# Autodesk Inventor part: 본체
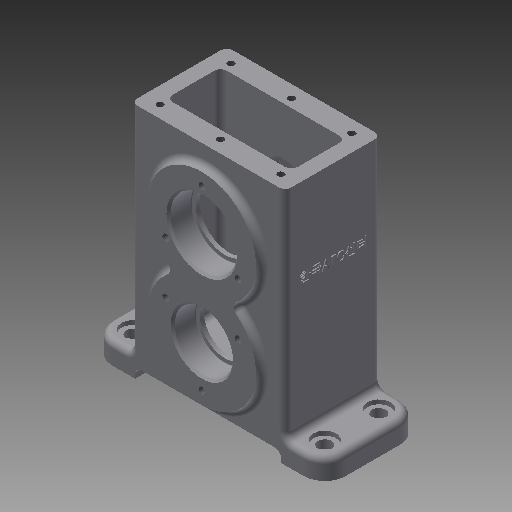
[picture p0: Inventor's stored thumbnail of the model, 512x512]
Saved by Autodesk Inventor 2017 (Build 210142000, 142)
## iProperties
Created: 2020-03
Part Number: 본체
Material: 알루미늄 6061
Document SubType Name: Modeling
Designer: mduedu
Density: 2.71 g/cm^3
Appearance: 기본값
Mass: 597.031 g
Surface Area: 576.062 cm^2
Volume: 220.307 cm^3
Author: mduedu
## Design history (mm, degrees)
sketch "스케치1"
  geometry: L1 (-56, 0)-(56, 0); L2 (56, 0)-(56, 10); L3 (-56, 10)-(-56, 0); L4 (37, 10)-(37, 114); L5 (37, 114)-(-37, 114); L6 (-37, 114)-(-37, 10); L7 (56, 10)-(37, 10); L8 (-37, 10)-(-56, 10); L9 (0, 0)-(0, 114); 1 further point
  constraints: 18 end point, 5 parallel, 2 midpoint, 2 vertical, 1 coincident, 1 horizontal, 1 perpendicular
  dimensions: "d0" = 112 distance of L1.start L1.end; "d2" = 10 distance of L1.end L2.end; "d3" = 114 distance between parallel lines of L5 L1; "d4" = 74 distance between parallel lines of L4 L6
extrude "돌출1" new body sketch "스케치1" stored distance "d5" = 46; taper "d6" = 0 deg
sketch "스케치2"
  geometry: L1 (56, 0)-(-56, 0) reference; C1 r 26 at (0, 34); C2 r 26 at (0, 79); 1 further point
  constraints: 2 centre point, 2 vertical alignment, 1 equal radius
  dimensions: "d7" = 52 diameter of C2; "d9" = 34 distance from line of C1.centre L1; "d10" = 45 distance of C2.centre C1.centre
extrude "돌출2" join sketch "스케치2" stored distance "d11" = 52; taper "d12" = 0 deg
fillet "모깎기1" dims "d13" = 3
fillet "모깎기2" dims "d14" = 3
fillet "모깎기3" dims "d15" = 10
fillet "모깎기4" dims "d16" = 3
fillet "모깎기5" dims "d17" = 3
sketch "스케치3"
  geometry: L1 (-30, 114)-(30, 114); L2 (30, 114)-(30, 13); L3 (30, 13)-(-30, 13); L4 (-30, 13)-(-30, 114); L5 (-34, 114)-(34, 114) reference; L6 (46, 0)-(-46, 0) reference; 2 further points
  constraints: 8 end point, 2 parallel, 1 collinear, 1 horizontal, 1 midpoint, 1 perpendicular, 1 vertical alignment
  dimensions: "d18" = 60 distance between parallel lines of L2 L4; "d20" = 13 distance between parallel lines of L3 L6
extrude "돌출3" cut sketch "스케치3" stored distance "d21" = 26; taper "d22" = 0 deg
fillet "모깎기6" dims "d23" = 3
fillet "모깎기7" dims "d24" = 3
sketch "스케치4"
  geometry: L1 (-35, 0)-(35, 0); L2 (35, 0)-(35, 5); L3 (35, 5)-(-35, 5); L4 (-35, 5)-(-35, 0); 2 further points
  constraints: 8 end point, 2 parallel, 1 coincident, 1 horizontal, 1 midpoint, 1 perpendicular
  dimensions: "d25" = 70 distance of L1.start L1.end; "d27" = 5 distance of L1.end L2.end
extrude "돌출4" cut sketch "스케치4" stored distance "d28" = 26; taper "d29" = 0 deg
fillet "모깎기8" dims "d30" = 3
sketch "스케치5"
  geometry: A1 r 10 centre (-86, 33) between (-86, 43) and (-96, 33) reference; A2 r 10 centre (-86, 7) between (-96, 7) and (-86, -3) reference; A3 r 10 centre (6, 7) between (6, -3) and (16, 7) reference; A4 r 10 centre (6, 33) between (16, 33) and (6, 43) reference; 5 further points
  constraints: 4 coincident
hole "구멍1" sketch "스케치5" at (-86, 33), (-86, 7), (6, 7), (6, 33) diameter "d31" = 6.6; stored, may be unused: countersink angle "d35" = 90 deg, drill point angle "d37" = 118 deg; dims "d32" = 6, "d33" = 11, "d34" = 2, "d36" = 8
sketch "스케치6"
  geometry: A1 r 26 centre (0, 34) between (-16.403, 54.172) and (16.403, 54.172) reference; A2 r 3 centre (18.296, 56.5) between (16.403, 58.828) and (16.403, 54.172) reference; A3 r 26 centre (0, 79) between (16.403, 58.828) and (-16.403, 58.828) reference; A4 r 3 centre (-18.296, 56.5) between (-16.403, 54.172) and (-16.403, 58.828) reference; 2 further points
  constraints: 1 coincident
hole "구멍2" sketch "스케치6" at (0, 79) diameter "d38" = 28; stored, may be unused: countersink angle "d42" = 90 deg, drill point angle "d44" = 118 deg; dims "d39" = 6, "d40" = 32, "d41" = 11, "d43" = 8
sketch "스케치7"
  geometry: C1 r 16 at (0, 79) reference; A1 r 26 centre (0, 34) between (-16.403, 54.172) and (16.403, 54.172) reference; A2 r 3 centre (18.296, 56.5) between (16.403, 58.828) and (16.403, 54.172) reference; A3 r 26 centre (0, 79) between (16.403, 58.828) and (-16.403, 58.828) reference; A4 r 3 centre (-18.296, 56.5) between (-16.403, 54.172) and (-16.403, 58.828) reference; 2 further points
  constraints: 1 coincident
hole "구멍3" sketch "스케치7" at (0, 34) diameter "d45" = 24; stored, may be unused: countersink angle "d49" = 90 deg, drill point angle "d51" = 118 deg; dims "d46" = 6, "d47" = 28, "d48" = 11, "d50" = 8
sketch "스케치8"
  geometry: C1 r 14 at (0, 34) reference; A1 r 26 centre (0, 34) between (-16.403, 54.172) and (16.403, 54.172) reference; A2 r 3 centre (18.296, 56.5) between (16.403, 58.828) and (16.403, 54.172) reference; A3 r 26 centre (0, 79) between (16.403, 58.828) and (-16.403, 58.828) reference; A4 r 3 centre (-18.296, 56.5) between (-16.403, 54.172) and (-16.403, 58.828) reference; 2 further points
  constraints: 1 coincident
hole "구멍4" sketch "스케치8" at (0, 79) diameter "d52" = 24; stored, may be unused: countersink angle "d56" = 90 deg, drill point angle "d58" = 118 deg; dims "d53" = 6, "d54" = 28, "d55" = 11, "d57" = 8
sketch "스케치9" dims "d59" = 40
  geometry: C1 r 14 at (0, 34) reference; C2 r 16 at (0, 79) reference; A1 r 26 centre (0, 34) between (-16.403, 54.172) and (16.403, 54.172) reference; A2 r 3 centre (18.296, 56.5) between (16.403, 58.828) and (16.403, 54.172) reference; A3 r 26 centre (0, 79) between (16.403, 58.828) and (-16.403, 58.828) reference; A4 r 3 centre (-18.296, 56.5) between (-16.403, 54.172) and (-16.403, 58.828) reference; 3 further points
  constraints: 2 vertical alignment, 1 coincident, 2 other
hole "구멍5" sketch "스케치9" at (0, 99) diameter "d61" = 3.242; stored, may be unused: countersink angle "d65" = 90 deg, drill point angle "d67" = 118 deg; dims "d62" = 8, "d63" = 28, "d64" = 11, "d66" = 10
sketch "스케치10" dims "d71" = 40
  geometry: C1 r 1.621 at (17.321, 69) reference; C2 r 1.621 at (-17.321, 69) reference; C3 r 1.621 at (0, 99) reference; C4 r 14 at (0, 34) reference; C5 r 16 at (0, 79) reference; A1 r 26 centre (0, 34) between (-16.403, 54.172) and (16.403, 54.172) reference; A2 r 3 centre (18.296, 56.5) between (16.403, 58.828) and (16.403, 54.172) reference; A3 r 26 centre (0, 79) between (16.403, 58.828) and (-16.403, 58.828) reference; A4 r 3 centre (-18.296, 56.5) between (-16.403, 54.172) and (-16.403, 58.828) reference; 3 further points
  constraints: 2 vertical alignment, 1 coincident, 2 other
hole "구멍6" sketch "스케치10" at (0, 14) diameter "d72" = 3.242; stored, may be unused: countersink angle "d76" = 90 deg, drill point angle "d78" = 118 deg; dims "d73" = 8, "d74" = 28, "d75" = 11, "d77" = 10
sketch "스케치11"
  geometry: L1 (5, 6)-(63, 6); L2 (63, 6)-(63, 40); L3 (63, 40)-(5, 40); L4 (5, 40)-(5, 6); L5 (5, 6)-(63, 40); L6 (63, 6)-(5, 40); 7 further points
  constraints: 12 end point, 4 coincident, 4 midpoint, 2 parallel, 1 horizontal, 1 perpendicular
  dimensions: "d82" = 58 distance of L3.end L2.end; "d83" = 34 distance of L2.end L1.end
hole "구멍7" sketch "스케치11" at (5, 40), (63, 40), (63, 6), (5, 6), (34, 6), (34, 40) diameter "d84" = 3.242; stored, may be unused: countersink angle "d88" = 90 deg, drill point angle "d90" = 118 deg; dims "d85" = 8, "d86" = 28, "d87" = 11, "d89" = 10
fillet "모깎기9" dims "d91" = 0.3
chamfer "모따기1" distance "d92" = 1; stored, may be unused: second distance "d93" = 2, angle "d94" = 45 deg
sketch "스케치12"
  geometry: 2 further points
  constraints: 1 coincident
hole "구멍8" sketch "스케치12" at (0, -23) diameter "d95" = 4.917; stored, may be unused: countersink angle "d99" = 90 deg, drill point angle "d101" = 118 deg; dims "d96" = 8, "d97" = 12, "d98" = 1, "d100" = 10
sketch "스케치13"
  geometry: L1 (33, -13)-(7, -13) reference; L2 (40, 101)-(0, 101) reference; 3 further points
  constraints: 1 midpoint, 1 vertical alignment, 1 other
  dimensions: "d102" = 40 distance from line of point (20, 61) L2
feature "엠보싱1" sketch "스케치13" dims "d0" = 112, "d2" = 10, "d3" = 114, "d4" = 74, "d13" = 3, "d103" = 0.5, "d104" = 0
node "솔리드1"
mirror "대칭1"
pattern_circular "원형 패턴1" dims angle "d69" = 360 deg
pattern_circular "원형 패턴2" dims angle "d80" = 360 deg
mirror "대칭2"
node "투영된 루프1"
node "투영된 루프2"
node "투영된 루프3"
node "투영된 루프4"
node "투영된 루프5"
